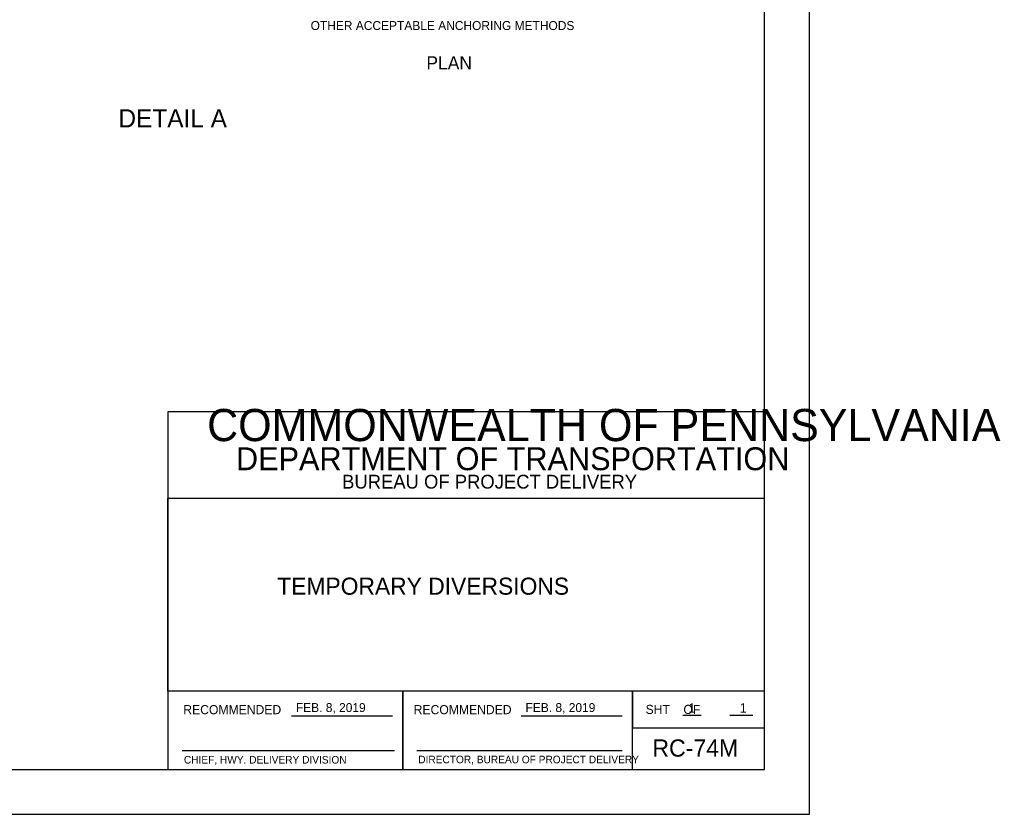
# Model space of a CAD drawing. Extents: x 636462 to 637367, y 299944 to 300538.
# Drawn here: x 637038.2 to 637367, y 299944.4 to 300210.9 of the extents above; entities that cross this region are included whole.
import ezdxf

# ---------------------------------------------------------------- set-up
doc = ezdxf.new("R2010")
doc.units = 0
for name, color, linetype in [('1', 7, 'Continuous'), ('Default', 7, 'Continuous'), ('PLT-BNDY', 7, 'Continuous')]:
    doc.layers.add(name, color=color, linetype=linetype)

msp = doc.modelspace()

# ---------------------------------------------------------------- linework, layer by layer
at = {"layer": '1'}
for p, q in [((637129.38, 299977.44), (637163.27, 299977.44)), ((637206.38, 299977.44), (637240.25, 299977.44)), ((637260.54, 299977.66), (637266.68, 299977.66)), ((637276.35, 299977.66), (637283.99, 299977.66)), ((637092.68, 299965.87), (637163.93, 299965.87)), ((637171.43, 299965.87), (637240.19, 299965.87))]:
    msp.add_line(p, q, dxfattribs=at)
msp.add_lwpolyline([(637287.91, 299959.45), (637287.91, 300523.45), (636501.91, 300523.45), (636501.91, 299959.45), (637287.91, 299959.45), (637287.91, 299985.81), (637087.91, 299985.81), (637087.91, 300050.49), (637287.91, 300050.49), (637287.91, 300079.45), (637087.91, 300079.45), (637087.91, 299959.45), (637166.72, 299959.45), (637166.72, 299985.81), (637166.72, 299959.45), (637243.72, 299959.45), (637243.72, 299985.81), (637243.72, 299973.49), (637287.91, 299973.49)], dxfattribs=at)
at = {"layer": 'PLT-BNDY'}
msp.add_lwpolyline([(636461.91, 300538.45), (637302.91, 300538.45), (637302.91, 299944.45), (636461.91, 299944.45)], close=True, dxfattribs=at)

# ---------------------------------------------------------------- texts
at = {"layer": '1'}
for s, height, p in [('COMMONWEALTH OF PENNSYLVANIA', 10.7834, (637101.07, 300069.59)), ('DEPARTMENT OF TRANSPORTATION', 7.6843, (637110.75, 300059.84)), ('BUREAU OF PROJECT DELIVERY', 4.6221, (637146.32, 300053.68)), ('RECOMMENDED', 3.048, (637093.08, 299978.04)), ('FEB. 8, 2019', 3, (637130.82, 299978.76)), ('RECOMMENDED', 3.048, (637170.32, 299978.04)), ('FEB. 8, 2019', 3, (637207.82, 299978.76)), ('SHT    OF', 3.048, (637248.08, 299978.12)), ('1', 3.13, (637262.41, 299978.54)), ('1', 3.13, (637279.64, 299978.59)), ('APPROVED', 0.0192, (637130.94, 299977.38)), ('APPROVED', 0.0192, (637130.94, 299977.38)), ('APPROVED', 0.0192, (637130.94, 299977.38)), ('APPROVED', 0.0192, (637130.94, 299977.38)), ('CHIEF, HWY. DELIVERY DIVISION', 2.54, (637093.29, 299961.49)), ('DIRECTOR, BUREAU OF PROJECT DELIVERY', 2.54, (637171.86, 299961.58))]:
    msp.add_text(s, height=height, dxfattribs=at).set_placement(p)
at = {"layer": 'Default'}
for s, height, p in [('OTHER ACCEPTABLE ANCHORING METHODS', 2.998, (637135.78, 300207.42)), ('PLAN', 4.372, (637174.6, 300194.22)), ('DETAIL A', 6.121, (637071.33, 300174.75)), ('TEMPORARY DIVERSIONS', 5.7257, (637124.58, 300018.1)), ('RC-74M', 5.779, (637250.37, 299963.81))]:
    msp.add_text(s, height=height, dxfattribs=at).set_placement(p)

doc.saveas('drawing.dxf')
